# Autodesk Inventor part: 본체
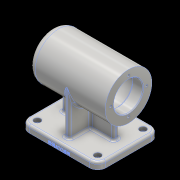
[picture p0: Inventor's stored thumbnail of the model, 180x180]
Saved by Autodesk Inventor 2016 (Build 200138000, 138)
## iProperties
Created: 2020-10
Part Number: 본체
Material: 알루미늄 6061
Document SubType Name: Modeling
Designer: 605-04
Density: 2.7 g/cm^3
Appearance: 알루미늄 - 평지
Mass: 1026.28 g
Surface Area: 757.983 cm^2
Volume: 380.103 cm^3
Author: 605-04
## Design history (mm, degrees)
sketch "스케치1"
  geometry: L1 (0, 0)-(0, 34); L2 (0, 34)-(112, 34); L3 (112, 34)-(112, 0); L4 (112, 0)-(0, 0); L5 (6, 0)-(6, 10.5); L6 (6, 10.5)-(9, 10.5); L7 (9, 10.5)-(9, 16); L8 (9, 16)-(13, 16); L9 (13, 16)-(13, 17.5); L10 (13, 17.5)-(31, 17.5); L11 (31, 17.5)-(31, 21); L12 (31, 21)-(43, 21); L13 (43, 21)-(43, 24); L14 (43, 24)-(97, 24); L15 (97, 24)-(97, 21); L16 (97, 21)-(112, 21)
  constraints: 32 end point, 14 perpendicular, 4 point on line, 1 vertical
  dimensions: "d1" = 21 diameter of L6 L4; "d2" = 32 diameter of L8 L4; "d3" = 35 diameter of L10 L4; "d4" = 42 diameter of L12 L4; "d5" = 48 diameter of L14 L4; "d6" = 3 distance between parallel lines of L7 L5; "d7" = 4 distance between parallel lines of L9 L7; "d8" = 18 distance between parallel lines of L11 L9; "d9" = 12 distance between parallel lines of L13 L11; "d10" = 54 distance between parallel lines of L15 L13; "d11" = 112 distance between parallel lines of L3 L1; "d12" = 15 distance between parallel lines of L3 L15; "d13" = 68 diameter of L2 L4
revolve "회전1" sketch "스케치1" stored, may be unused: angle "d14" = 90 deg
node "작업 평면1"
sketch "스케치2"
  geometry: L1 (112, -45)-(0, -45); L2 (0, -45)-(0, 45); L3 (0, 45)-(112, 45); L4 (112, 45)-(112, -45); L5 (112, -45)-(0, 45); L6 (0, -45)-(112, 45); L7 (112, -34)-(112, 34) reference; 3 further points
  constraints: 12 end point, 3 midpoint, 2 parallel, 1 collinear, 1 horizontal, 1 horizontal alignment, 1 perpendicular
  dimensions: "d16" = 112 distance of L2.end L3.end; "d17" = 90 distance of L3.end L1.start
extrude "돌출1" join sketch "스케치2" distance "d18" = 10; taper "d19" = 0 deg
sketch "스케치3"
  geometry: L1 (112, 45)-(112, -45) reference; L2 (112, -45)-(0, -45) reference; L3 (52, -34)-(60, -34); L4 (60, -34)-(60, 34); L5 (60, 34)-(52, 34); L6 (52, 34)-(52, -34); L7 (52, -34)-(60, 34); L8 (60, -34)-(52, 34); L9 (0, 45)-(112, 45) reference; L10 (18, 4)-(94, 4); L11 (94, 4)-(94, -4); L12 (94, -4)-(18, -4); L13 (18, -4)-(18, 4); L14 (18, 4)-(94, -4); L15 (94, 4)-(18, -4); 2 further points
  constraints: 24 end point, 4 midpoint, 4 parallel, 2 horizontal, 2 perpendicular
  dimensions: "d23" = 56 distance from line of L1 point (56, 0); "d24" = 45 distance from line of L9 point (56, 0); "d25" = 8 distance of L4.end L5.end; "d26" = 68 distance of L3.end L4.end; "d29" = 8 distance of L10.end L11.end; "d30" = 76 distance of L11.end L12.end
extrude "돌출2" join sketch "스케치3" stored distance "d27" = 10; taper "d28" = 0 deg
sketch "스케치4"
  geometry: L1 (0, 0)-(-26, 0); C1 r 34 at (0, 0) reference; C2 r 21 at (0, 0) reference; 1 further point
  constraints: 2 end point, 1 horizontal
  dimensions: "d31" = 26 distance of L1.start L1.end
hole "구멍1" sketch "스케치4" at (-26, 0) diameter "d32" = 3.242; stored, may be unused: countersink angle "d36" = 90 deg, drill point angle "d38" = 118 deg; dims "d33" = 8, "d34" = 4, "d35" = 2, "d37" = 11
sketch "스케치5"
  geometry: L1 (112, -45)-(0, -45) reference; L2 (0, -45)-(0, 45) reference; L3 (0, 45)-(112, 45) reference; L4 (112, 45)-(112, -45) reference; 2 further points
  dimensions: "d42" = 12 distance from line of L1 point (12, -33); "d43" = 12 distance from line of L2 point (12, -33)
hole "구멍2" sketch "스케치5" at (12, -33) diameter "d44" = 5.5; stored, may be unused: countersink angle "d48" = 90 deg, drill point angle "d50" = 118 deg; dims "d45" = 8, "d46" = 9.5, "d47" = 5.4, "d49" = 10
fillet "모깎기1" dims "d57" = 3
fillet "모깎기2" dims "d58" = 12
fillet "모깎기3" dims "d59" = 3
fillet "모깎기4" dims "d60" = 0.3
fillet "모깎기5" dims "d61" = 3
fillet "모깎기6" dims "d62" = 3
chamfer "모따기1" distance "d63" = 1; stored, may be unused: second distance "d64" = 2, angle "d65" = 45 deg
fillet "모깎기7" dims "d66" = 10
sketch "스케치6"
  geometry: L1 (30.079, 4.97)-(57.921, 4.97); L2 (57.921, 4.97)-(57.921, 1.03); L3 (57.921, 1.03)-(30.079, 1.03); L4 (30.079, 1.03)-(30.079, 4.97); L5 (30.079, 3)-(44, 3); L6 (44, 4.97)-(44, 3); L7 (100, 0)-(100, 7) reference; L8 (88, 0)-(0, 0) reference; 1 further point
  constraints: 4 end point, 2 midpoint, 2 other
  dimensions: "d67" = 56 distance from line of L7 L5.end; "d68" = 3 distance between parallel lines of L8 L5
feature "엠보싱1" sketch "스케치6" dims "d1" = 21, "d2" = 32, "d3" = 35, "d4" = 42, "d5" = 48, "d6" = 3, "d7" = 4, "d8" = 18, "d9" = 12, "d10" = 54, "d11" = 112, "d12" = 15, "d13" = 68, "d16" = 112, "d17" = 90, "d69" = 0.5, "d70" = 0
node "솔리드1"
pattern_circular "원형 패턴1" dims angle "d40" = 360 deg
pattern_linear "직사각형 패턴1" dims "d53" = 66, "d56" = 88
node "투영된 루프1"
node "투영된 루프2"
other parameters: "d15" = -74
